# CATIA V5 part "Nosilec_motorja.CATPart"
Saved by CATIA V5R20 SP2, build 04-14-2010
Part number: Nosilec_motorja
Bounding box of the stored display mesh (mm): x -23.1 to 23.1, y -17.5 to 20.5, z -3 to 3
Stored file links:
  C:\Documents and Settings\Administrator\My Documents\Hobi_dokumenti\CAD_CNC\Clap_CATIA\Nosilec_motorja.CATPart
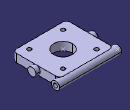
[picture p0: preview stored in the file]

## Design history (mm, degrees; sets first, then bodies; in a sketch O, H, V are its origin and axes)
Set1
  Point1: type Center, Curve edge [end face of Pad1 | face of Pad1 from Sketch1.A1]
  Plane1: stored without definition
  Point2: type Center, Curve edge [end face of Pad2 | face of Pad2]
  Plane2: stored without definition
Body1 (main body)
  Sketch1 on xy-plane, origin (0, 0, 0), H (1, 0, 0), V (0, 1, 0)
    line L1 (-20, 17.5) -> (20, 17.5)
    line L2 (20, 17.5) -> (20, -17.5)
    line L3 (20, -17.5) -> (-20, -17.5)
    line L4 (-20, -17.5) -> (-20, 17.5)
    reference intersected line E2 through (0, 0) direction (0, 1) from yz-plane
    reference intersected line E3 through (0, 0) direction (-1, 0) from zx-plane
    circle A1 centre (0, 0) radius 7
    circle A2 centre (-12.5, 12.5) radius 1.5
    point P5 (-12.5, 12.5)
    circle A3 centre (-12.5, -12.5) radius 1.5
    circle A4 centre (12.5, -12.5) radius 1.5
    circle A5 centre (12.5, 12.5) radius 1.5
    distance E2 L2 = 20
    distance E2 L4 = 20
    distance L1 L3 = 35
    distance E3 L3 = 17.5
    radius A1 = 7
    radius A2 = 1.5
    distance V P5 = 12.5
    distance H P5 = 12.5
    horizontal: L1 H, L3 H, E3 H
    vertical: L2 V, L4 V, E2 V
    perpendicularity: E2 L1
    symmetry: A2 A3 H, A3 A4 V, A2 A5 V
  Pad1: profile Sketch1, direction (0, 0, 1), length 3, mirrored extent
  Fillet1: radius 3, on edge [face of Pad1 from Sketch1.L3 | face of Pad1 from Sketch1.L4]; edge [face of Pad1 from Sketch1.L2 | face of Pad1 from Sketch1.L3]; edge [face of Pad1 from Sketch1.L4 | face of Pad1 from Sketch1.L1]; edge [face of Pad1 from Sketch1.L1 | face of Pad1 from Sketch1.L2]
  Sketch2 on face of Pad1 from Sketch1.L4, origin (-20, 0, 0), H (0, -1, 0), V (0, 0, 1)
    circle A1 centre (-17.5, 0) radius 3
    point P1 (-17.5, 0)
    circle A2 centre (-17.5, 0) radius 1.5
    radius A1 = 3
    radius A2 = 1.5
    distance P1 H = 0
    distance P1 V = 17.5
  Pad2: profile Sketch2, direction (-1, 0, 0), length 3.1
  Mirror1: of Pad2, Sketch2, about Plane1
  Pad3: profile face of Mirror1, direction along edge [start face of Pad1 | face of Pad1 from Sketch1.L1], up to start face of Pad2
  Sketch3 on end face of Pad2, origin (-23.1, 0, 0), H (0, -1, 0), V (0, 0, 1)
    circle A1 centre (-17.5, 0) radius 1.5
    point P1 (-17.5, 0)
    reference projected point E1 (-17.5, 0) from Point2
    radius A1 = 1.5
    distance P1 E1 = 0
  Pocket1: profile Sketch3, direction (1, 0, 0), through (limit type 3)
  Sketch4 on face of Pad1 from Sketch1.L2, origin (20, 0, 0), H (0, 1, 0), V (0, 0, 1)
    circle A1 centre (0, 0) radius 3
    point P1 (0, 0)
    radius A1 = 3
    distance P1 V = 0
    distance P1 H = 0
  Pad4: profile Sketch4, direction (1, 0, 0), length 3.1
  Mirror2: of Pad4, Sketch4, about Plane2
